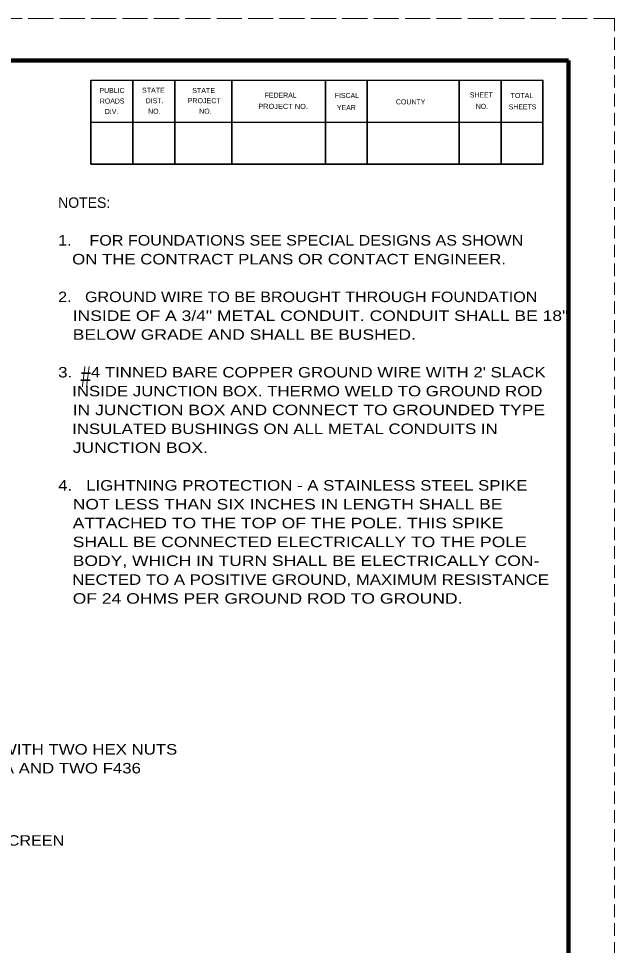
# Model space of a CAD drawing. Extents: x -1 to 679, y 0 to 440.
# Drawn here: x 536.2 to 678.6, y 218.4 to 439.6 of the extents above; entities that cross this region are included whole.
import ezdxf
from ezdxf.enums import TextEntityAlignment as Align

# ---------------------------------------------------------------- set-up
doc = ezdxf.new("R2010")
doc.units = 0
doc.linetypes.add('LONG_DASHED', pattern=[7.5, 6, -1.5])
doc.linetypes.add('MEDIUM_DASHED', pattern=[4.5, 3, -1.5])
doc.layers.add('1', color=7, linetype='Continuous', lineweight=35)
doc.layers.add('61', color=7, linetype='Continuous', lineweight=35)

msp = doc.modelspace()

# ---------------------------------------------------------------- linework, layer by layer
at = {"layer": '1', "linetype": 'MEDIUM_DASHED', "lineweight": 13}
msp.add_line((678.595, 439.645), (678.575, -0.375), dxfattribs=at)
at = {"layer": '61', "linetype": 'LONG_DASHED', "lineweight": 13}
msp.add_line((-1.425, 439.645), (678.595, 439.645), dxfattribs=at)
at = {"layer": '61', "lineweight": 158}
msp.add_line((667.615, 429.645), (667.635, 9.605), dxfattribs=at)
at = {"layer": '61'}
for p, q in [((563.535, 424.885), (563.535, 404.885)), ((573.535, 424.885), (573.535, 404.885)), ((587.215, 424.885), (587.215, 404.885)), ((609.535, 424.885), (609.535, 404.885)), ((619.535, 424.885), (619.535, 404.885)), ((641.515, 424.905), (641.515, 404.905)), ((651.515, 424.905), (651.515, 404.905)), ((661.535, 414.865), (553.515, 414.885))]:
    msp.add_line(p, q, dxfattribs=at)
at = {"layer": '61', "lineweight": 158}
msp.add_lwpolyline([(667.615, 429.645), (28.575, 429.645), (28.575, 9.625)], dxfattribs=at)
at = {"layer": '61'}
for points in [[(661.515, 424.905), (553.535, 424.885), (553.535, 404.885)], [(661.515, 424.905), (661.515, 404.905), (553.535, 404.885)]]:
    msp.add_lwpolyline(points, dxfattribs=at)

# ---------------------------------------------------------------- texts
at = {"layer": '1'}
msp.add_text('NOTES:', height=2.5, dxfattribs=at).set_placement((545.702, 394.452))
msp.add_text('NOTES:', height=2.5, dxfattribs=at).set_placement((545.702, 394.452))
for s, width, p in [('1.    FOR FOUNDATIONS SEE SPECIAL DESIGNS AS SHOWN', 1.15, (545.702, 385.452)), ('1.    FOR FOUNDATIONS SEE SPECIAL DESIGNS AS SHOWN', 1.15, (545.702, 385.452)), ('   ON THE CONTRACT PLANS OR CONTACT ENGINEER.', 1.2, (545.702, 380.952)), ('   ON THE CONTRACT PLANS OR CONTACT ENGINEER.', 1.2, (545.702, 380.952)), ('2.   GROUND WIRE TO BE BROUGHT THROUGH FOUNDATION', 1.15, (545.702, 371.952)), ('2.   GROUND WIRE TO BE BROUGHT THROUGH FOUNDATION', 1.15, (545.702, 371.952)), ('   INSIDE OF A 3/4" METAL CONDUIT. CONDUIT SHALL BE 18"', 1.25, (545.702, 367.452)), ('   INSIDE OF A 3/4" METAL CONDUIT. CONDUIT SHALL BE 18"', 1.25, (545.702, 367.452)), ('   BELOW GRADE AND SHALL BE BUSHED.', 1.25, (545.702, 362.952)), ('   BELOW GRADE AND SHALL BE BUSHED.', 1.25, (545.702, 362.952)), ("3.    4 TINNED BARE COPPER GROUND WIRE WITH 2' SLACK", 1.2, (545.702, 353.952)), ("3.    4 TINNED BARE COPPER GROUND WIRE WITH 2' SLACK", 1.2, (545.702, 353.952)), ('   INSIDE JUNCTION BOX. THERMO WELD TO GROUND ROD', 1.2, (545.702, 349.452)), ('   INSIDE JUNCTION BOX. THERMO WELD TO GROUND ROD', 1.2, (545.702, 349.452)), ('   IN JUNCTION BOX AND CONNECT TO GROUNDED TYPE', 1.25, (545.702, 344.952)), ('   IN JUNCTION BOX AND CONNECT TO GROUNDED TYPE', 1.25, (545.702, 344.952)), ('   INSULATED BUSHINGS ON ALL METAL CONDUITS IN', 1.2, (545.702, 340.452)), ('   INSULATED BUSHINGS ON ALL METAL CONDUITS IN', 1.2, (545.702, 340.452)), ('   JUNCTION BOX.', 1.25, (545.702, 335.952)), ('   JUNCTION BOX.', 1.25, (545.702, 335.952)), ('4.   LIGHTNING PROTECTION - A STAINLESS STEEL SPIKE', 1.2, (545.702, 326.952)), ('4.   LIGHTNING PROTECTION - A STAINLESS STEEL SPIKE', 1.2, (545.702, 326.952)), ('   NOT LESS THAN SIX INCHES IN LENGTH SHALL BE', 1.25, (545.702, 322.452)), ('   NOT LESS THAN SIX INCHES IN LENGTH SHALL BE', 1.25, (545.702, 322.452)), ('   ATTACHED TO THE TOP OF THE POLE. THIS SPIKE', 1.25, (545.702, 317.952)), ('   ATTACHED TO THE TOP OF THE POLE. THIS SPIKE', 1.25, (545.702, 317.952)), ('   SHALL BE CONNECTED ELECTRICALLY TO THE POLE', 1.25, (545.702, 313.452)), ('   SHALL BE CONNECTED ELECTRICALLY TO THE POLE', 1.25, (545.702, 313.452)), ('   BODY, WHICH IN TURN SHALL BE ELECTRICALLY CON-', 1.25, (545.702, 308.952)), ('   BODY, WHICH IN TURN SHALL BE ELECTRICALLY CON-', 1.25, (545.702, 308.952)), ('   NECTED TO A POSITIVE GROUND, MAXIMUM RESISTANCE', 1.2, (545.702, 304.452)), ('   NECTED TO A POSITIVE GROUND, MAXIMUM RESISTANCE', 1.2, (545.702, 304.452)), ('   OF 24 OHMS PER GROUND ROD TO GROUND.', 1.25, (545.702, 299.952)), ('   OF 24 OHMS PER GROUND ROD TO GROUND.', 1.25, (545.702, 299.952)), ('EACH BOLT PROVIDED WITH TWO HEX NUTS', 1.2, (486.114, 263.93)), ('MEETING A563, GRADE A AND TWO F436', 1.2, (486.114, 259.43))]:
    msp.add_text(s, height=2.5, dxfattribs=dict(at, width=width)).set_placement(p)
for s, height, width, p in [('#', 5, 0.65, (552.302, 351.66)), ('INSTALL VARMINT SCREEN', 2.5, 1.15, (521.609, 242.181))]:
    msp.add_text(s, height=height, dxfattribs=dict(at, width=width)).set_placement(p, align=Align.CENTER)
at = {"layer": '61'}
for s, rotation, p in [('PUBLIC', 0.033, (555.575, 421.865)), ('ROADS', 0.124, (555.655, 419.345)), ('DIST.', 0.056, (566.615, 419.425)), ('FEDERAL', 0.007, (595.035, 420.745)), ('FISCAL', 359.942, (611.775, 420.685)), ('SHEET', 0.059, (644.035, 420.805)), ('YEAR', 0.105, (612.295, 417.785)), ('COUNTY', 0.069, (626.395, 419.145)), ('SHEETS', 359.959, (653.315, 417.965)), ('DIV.', 359.932, (556.855, 416.845))]:
    msp.add_text(s, height=1.201, rotation=rotation, dxfattribs=at).set_placement(p)
for s, rotation, width, p in [('STATE', 0.059, 1.05, (565.735, 421.925)), ('STATE', 0.059, 1.05, (577.735, 421.865)), ('PROJECT', 359.908, 1.05, (576.655, 419.445)), ('TOTAL', 359.926, 1.05, (653.775, 420.665)), ('PROJECT NO.', 359.922, 1.1, (593.495, 418.085)), ('NO.', 359.852, 0.95, (645.455, 418.085)), ('NO.', 359.852, 0.95, (567.195, 416.905)), ('NO.', 0.225, 0.95, (579.395, 416.905))]:
    msp.add_text(s, height=1.201, rotation=rotation, dxfattribs=dict(at, width=width)).set_placement(p)

doc.saveas('drawing.dxf')
